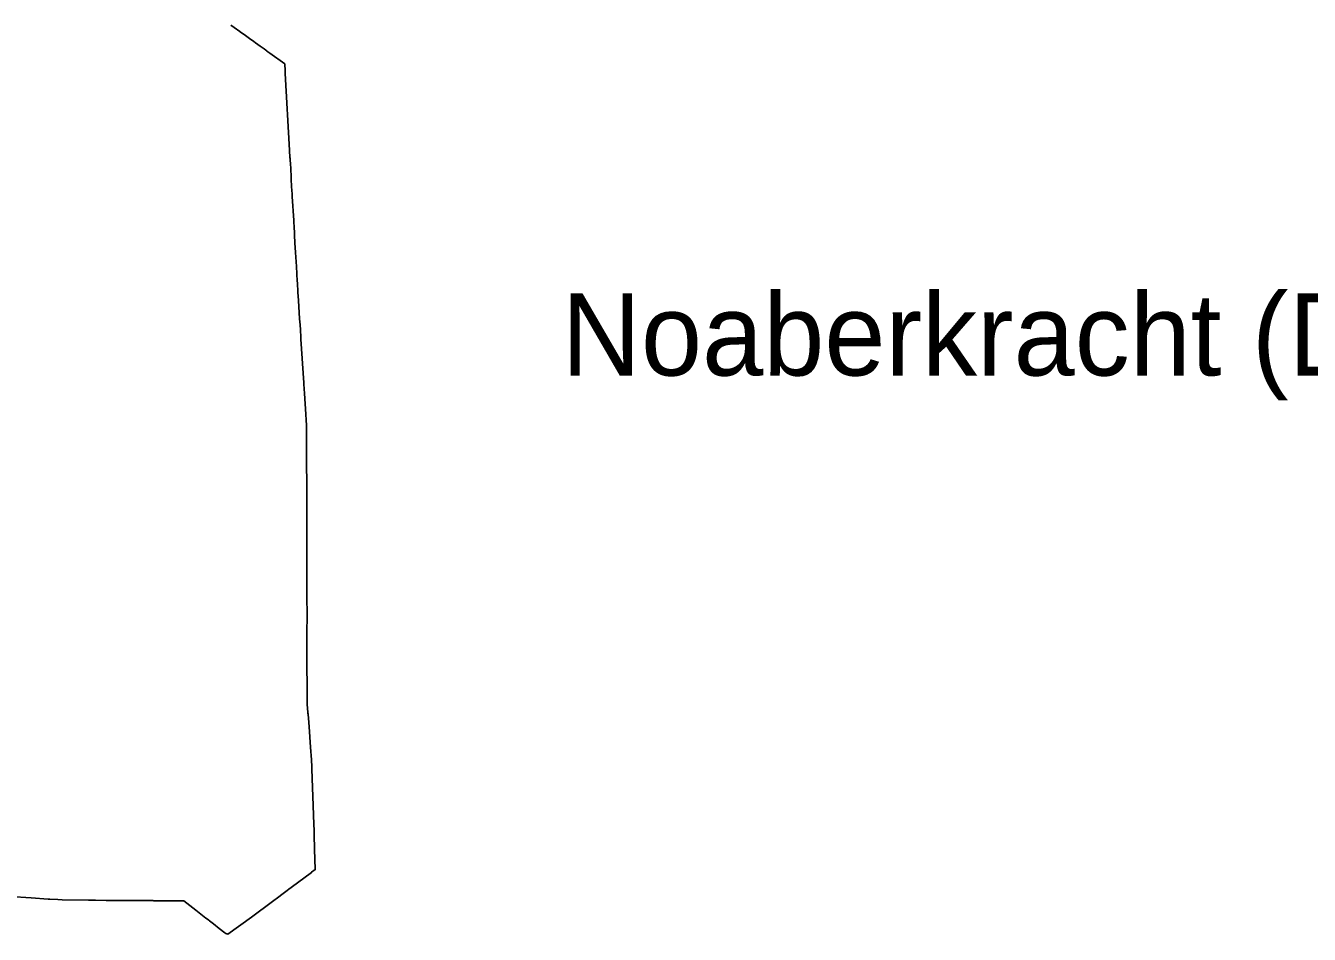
# Model space of a CAD drawing. Extents: x 113371 to 291721, y 393993 to 520143.
# Drawn here: x 253770 to 261580, y 486853 to 492383 of the extents above; entities that cross this region are included whole.
import ezdxf

# ---------------------------------------------------------------- set-up
doc = ezdxf.new("R2010")
doc.units = 0
doc.layers.add('Default', color=7, linetype='Continuous')
doc.layers.add('plaatsnamen', color=7, linetype='Continuous')

msp = doc.modelspace()

# ---------------------------------------------------------------- linework, layer by layer
at = {"layer": 'Default'}
for points in [[(255019.515625, 492385.2625), (255039.075625, 492371.2525), (255072.655625, 492347.2025), (255076.025625, 492344.7925), (255089.395625, 492335.2125), (255099.235625, 492328.1625), (255131.885625, 492304.6425), (255158.335625, 492285.5825), (255168.105625, 492278.5325), (255197.425625, 492257.4125), (255220.445625, 492240.8125), (255231.955625, 492232.5225), (255237.525625, 492228.5125), (255237.315625, 492228.2625), (255256.675625, 492214.4525), (255347.005625, 492150.0325), (255349.295625, 492107.4825), (255349.225625, 492099.7025), (255349.625625, 492092.3225), (255374.855625, 491624.3125), (255375.725625, 491608.1425)], [(255231.955625, 492232.5225), (255220.445625, 492240.8125), (255197.425625, 492257.4125), (255168.105625, 492278.5325), (255158.335625, 492285.5825), (255131.885625, 492304.6425), (255099.235625, 492328.1625), (255089.395625, 492335.2125), (255076.025625, 492344.7925), (255072.655625, 492347.2025), (255039.075625, 492371.2525), (255019.515625, 492385.2625)], [(255430.295625, 490709.9725), (255427.095625, 490761.2725), (255426.825625, 490765.6125), (255423.895625, 490812.6025), (255423.715625, 490815.4325), (255423.535625, 490818.3925), (255422.885625, 490828.7325), (255417.335625, 490917.7925), (255412.115625, 491001.5725), (255408.435625, 491060.5025), (255406.125625, 491107.8825), (255405.965625, 491111.2525), (255405.305625, 491123.9825), (255405.205625, 491125.6325), (255403.715625, 491151.7225), (255401.325625, 491193.5525), (255401.105625, 491197.0825), (255392.315625, 491342.1025), (255391.075625, 491362.4625), (255390.455625, 491375.0325), (255388.665625, 491388.4525), (255388.355625, 491396.4825), (255383.675625, 491517.7525), (255383.105625, 491523.9025), (255382.445625, 491531.0625), (255378.485625, 491573.7925), (255377.815625, 491581.0425), (255376.445625, 491594.9125), (255375.725625, 491608.1425), (255374.855625, 491624.3125), (255349.625625, 492092.3225), (255349.225625, 492099.7025), (255349.295625, 492107.4825), (255347.005625, 492150.0325), (255256.675625, 492214.4525), (255237.315625, 492228.2625), (255237.525625, 492228.5125), (255231.955625, 492232.5225)], [(255375.725625, 491608.1425), (255376.445625, 491594.9125), (255377.815625, 491581.0425), (255378.485625, 491573.7925), (255382.445625, 491531.0625), (255383.105625, 491523.9025), (255383.675625, 491517.7525), (255388.355625, 491396.4825), (255388.665625, 491388.4525), (255390.455625, 491375.0325), (255391.075625, 491362.4625), (255392.315625, 491342.1025), (255401.105625, 491197.0825), (255401.325625, 491193.5525), (255403.715625, 491151.7225), (255405.205625, 491125.6325), (255405.305625, 491123.9825), (255405.965625, 491111.2525), (255406.125625, 491107.8825), (255408.435625, 491060.5025), (255412.115625, 491001.5725), (255417.335625, 490917.7925), (255422.885625, 490828.7325), (255423.535625, 490818.3925), (255423.715625, 490815.4325), (255423.895625, 490812.6025), (255426.825625, 490765.6125), (255427.095625, 490761.2725), (255430.295625, 490709.9725), (255437.215625, 490598.8925), (255439.565625, 490561.2625), (255441.395625, 490531.7925), (255444.185625, 490487.9425), (255444.895625, 490476.8125), (255444.985625, 490475.4225), (255462.005625, 490208.4625), (255462.505625, 490200.4725), (255466.105625, 490144.0225)], [(255481.885625, 488835.7925), (255481.825625, 488867.4425), (255481.825625, 488869.4725), (255481.805625, 488876.8025), (255481.775625, 488891.9325), (255481.775625, 488894.0325), (255481.545625, 489010.7025), (255481.095625, 489178.5425), (255481.015625, 489199.5125), (255480.985625, 489207.6825), (255480.955625, 489218.3325), (255480.395625, 489372.6625), (255480.395625, 489372.7525), (255480.395625, 489373.7425), (255480.205625, 489418.6525), (255480.265625, 489512.4725), (255480.015625, 489536.6125), (255479.995625, 489548.5525), (255479.995625, 489551.7625), (255479.655625, 489760.0225), (255479.655625, 489760.8825), (255479.625625, 489773.5525), (255479.315625, 489818.7425), (255479.175625, 489848.4325), (255478.865625, 489918.2325), (255478.715625, 489951.5425), (255476.565625, 489982.7925), (255474.125625, 490018.1525), (255466.105625, 490144.0225), (255462.505625, 490200.4725), (255462.005625, 490208.4625), (255444.985625, 490475.4225), (255444.895625, 490476.8125), (255444.185625, 490487.9425), (255441.395625, 490531.7925), (255439.565625, 490561.2625), (255437.215625, 490598.8925), (255430.295625, 490709.9725)], [(255466.105625, 490144.0225), (255474.125625, 490018.1525), (255476.565625, 489982.7925), (255478.715625, 489951.5425), (255478.865625, 489918.2325), (255479.175625, 489848.4325), (255479.315625, 489818.7425), (255479.625625, 489773.5525), (255479.655625, 489760.8825), (255479.655625, 489760.0225), (255479.995625, 489551.7625), (255479.995625, 489548.5525), (255480.015625, 489536.6125), (255480.265625, 489512.4725), (255480.205625, 489418.6525), (255480.395625, 489373.7425), (255480.395625, 489372.7525), (255480.395625, 489372.6625), (255480.955625, 489218.3325), (255480.985625, 489207.6825), (255481.015625, 489199.5125), (255481.095625, 489178.5425), (255481.545625, 489010.7025), (255481.775625, 488894.0325), (255481.775625, 488891.9325), (255481.805625, 488876.8025), (255481.825625, 488869.4725), (255481.825625, 488867.4425), (255481.885625, 488835.7925), (255481.675625, 488645.1025), (255481.655625, 488596.6125), (255481.655625, 488594.8025), (255481.625625, 488498.9725), (255481.625625, 488467.7825), (255481.615625, 488455.5425), (255481.615625, 488434.0425), (255482.015625, 488415.8425), (255482.235625, 488394.8825)], [(255143.735625, 486957.8125), (255271.685625, 487053.1225), (255309.785625, 487081.5025), (255329.085625, 487095.8725), (255361.765625, 487120.2225), (255371.205625, 487127.2525), (255386.045625, 487138.3225), (255509.005625, 487230.3125), (255509.505625, 487230.6925), (255531.785625, 487247.3525), (255528.245625, 487371.4325), (255528.145625, 487374.1325), (255525.275625, 487457.4025), (255524.495625, 487480.1325), (255521.245625, 487574.5725), (255521.065625, 487579.7725), (255511.435625, 487859.2625), (255510.945625, 487873.1625), (255509.505625, 487914.4625), (255503.835625, 487992.2725), (255494.325625, 488115.7225), (255492.145625, 488142.7525), (255488.005625, 488193.9125), (255487.645625, 488198.8925), (255487.355625, 488202.8825), (255483.615625, 488254.5025), (255483.245625, 488295.6125), (255482.375625, 488381.0625), (255482.235625, 488394.8825), (255482.015625, 488415.8425), (255481.615625, 488434.0425), (255481.615625, 488455.5425), (255481.625625, 488467.7825), (255481.625625, 488498.9725), (255481.655625, 488594.8025), (255481.655625, 488596.6125), (255481.675625, 488645.1025), (255481.885625, 488835.7925)], [(255482.235625, 488394.8825), (255482.375625, 488381.0625), (255483.245625, 488295.6125), (255483.615625, 488254.5025), (255487.355625, 488202.8825), (255487.645625, 488198.8925), (255488.005625, 488193.9125), (255492.145625, 488142.7525), (255494.325625, 488115.7225), (255503.835625, 487992.2725), (255509.505625, 487914.4625), (255510.945625, 487873.1625), (255511.435625, 487859.2625), (255521.065625, 487579.7725), (255521.245625, 487574.5725), (255524.495625, 487480.1325), (255525.275625, 487457.4025), (255528.145625, 487374.1325), (255528.245625, 487371.4325), (255531.785625, 487247.3525), (255509.505625, 487230.6925), (255509.005625, 487230.3125), (255386.045625, 487138.3225), (255371.205625, 487127.2525), (255361.765625, 487120.2225), (255329.085625, 487095.8725), (255309.785625, 487081.5025), (255271.685625, 487053.1225), (255143.735625, 486957.8125), (255000.785625, 486853.3225), (254988.485625, 486858.7725), (254982.145625, 486862.1125), (254947.855625, 486889.3625), (254913.255625, 486916.6925), (254889.005625, 486935.8425), (254883.985625, 486939.6325), (254870.125625, 486950.0925), (254867.425625, 486952.1325)], [(254867.425625, 486952.1325), (254805.915625, 486999.8525), (254731.965625, 487057.2225), (254731.725625, 487057.2125), (254693.165625, 487056.3625), (254668.175625, 487057.1825), (254657.455625, 487057.2225), (254574.085625, 487057.5825), (254549.495625, 487057.6925), (254547.645625, 487058.0025), (254545.785625, 487058.2525), (254543.905625, 487058.4325), (254542.035625, 487058.5425), (254540.155625, 487058.5825), (254538.275625, 487058.5625), (254536.395625, 487058.4725), (254524.675625, 487058.3625), (254515.515625, 487058.6125), (254444.005625, 487059.4225), (254357.095625, 487059.7825), (254276.355625, 487060.1125), (254259.195625, 487060.1825), (254195.285625, 487060.4525), (254175.055625, 487060.5425), (254152.815625, 487060.8225), (253991.715625, 487062.8425), (253965.955625, 487064.4925), (253917.805625, 487067.5625), (253908.235625, 487068.1725), (253804.395625, 487074.8025), (253675.135625, 487083.0425)], [(253675.135625, 487083.0425), (253804.395625, 487074.8025), (253908.235625, 487068.1725)], [(253908.235625, 487068.1725), (253917.805625, 487067.5625), (253965.955625, 487064.4925), (253991.715625, 487062.8425), (254152.815625, 487060.8225), (254175.055625, 487060.5425), (254195.285625, 487060.4525), (254259.195625, 487060.1825), (254276.355625, 487060.1125), (254357.095625, 487059.7825), (254444.005625, 487059.4225), (254515.515625, 487058.6125), (254524.675625, 487058.3625), (254536.395625, 487058.4725), (254538.275625, 487058.5625), (254540.155625, 487058.5825), (254542.035625, 487058.5425), (254543.905625, 487058.4325), (254545.785625, 487058.2525), (254547.645625, 487058.0025), (254549.495625, 487057.6925), (254574.085625, 487057.5825), (254657.455625, 487057.2225), (254668.175625, 487057.1825), (254693.165625, 487056.3625), (254731.725625, 487057.2125), (254731.965625, 487057.2225), (254805.915625, 486999.8525), (254867.425625, 486952.1325), (254870.125625, 486950.0925), (254883.985625, 486939.6325), (254889.005625, 486935.8425), (254913.255625, 486916.6925), (254947.855625, 486889.3625), (254982.145625, 486862.1125), (254988.485625, 486858.7725), (255000.785625, 486853.3225), (255143.735625, 486957.8125)]]:
    msp.add_lwpolyline(points, dxfattribs=at)

# ---------------------------------------------------------------- texts
at = {"layer": 'plaatsnamen'}
msp.add_text('Noaberkracht (Dinkelland)', height=500, dxfattribs=at).set_placement((257030.765957, 490253.704815))

doc.saveas('drawing.dxf')
